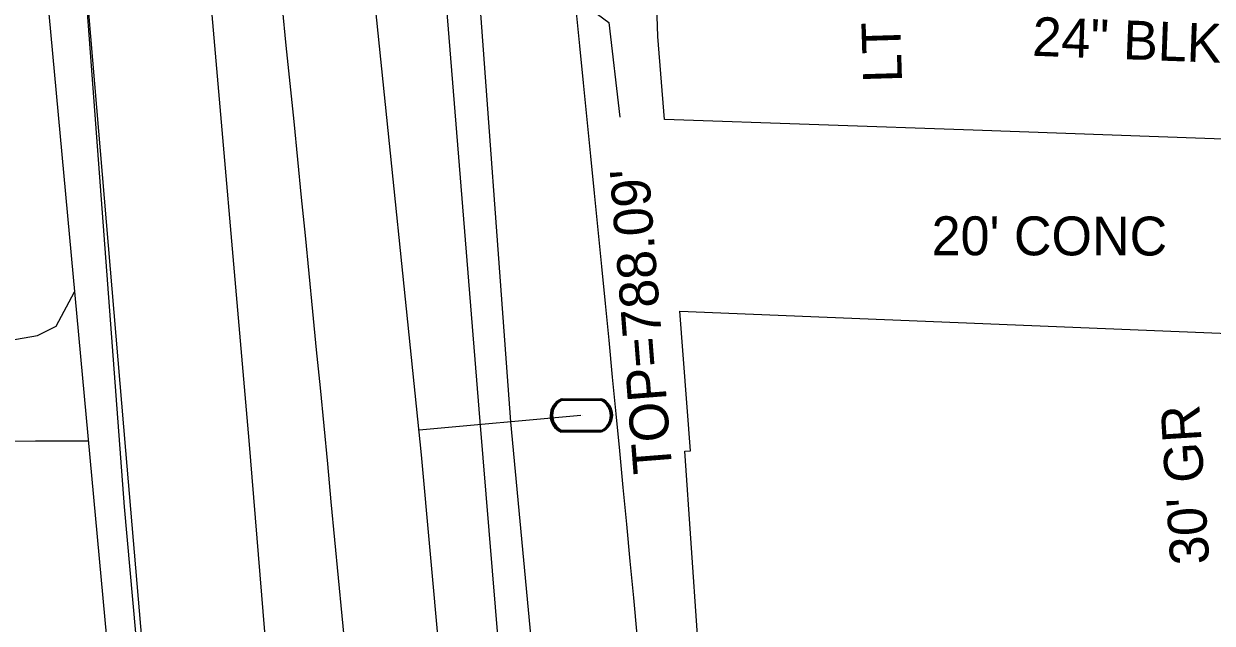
# Model space of a CAD drawing. Extents: x 1627482 to 1629573, y 760826 to 766301.
# Drawn here: x 1628290.6 to 1628412.7, y 765178.3 to 765240 of the extents above; entities that cross this region are included whole.
import ezdxf

# ---------------------------------------------------------------- set-up
doc = ezdxf.new("R2010")
doc.units = 0
for name, color, linetype in [('Exist Building Text', 7, 'Continuous'), ('Exist Horizontal Alignment', 7, 'Continuous'), ('Exist Right of Way Line', 7, 'Continuous'), ('Exist Roads EOP', 7, 'Continuous'), ('Exist Roads EOP Other', 7, 'Continuous'), ('Exist Roads EOP Other Text', 7, 'Continuous'), ('Exist Roads EOT', 7, 'Continuous'), ('Exist Roads Soil', 7, 'Continuous'), ('Exist Roads Soil Text', 7, 'Continuous'), ('Exist Structure Minor Catch Basin Leader', 7, 'Continuous'), ('Exist Structure Minor Catch Basin Top Elevation', 7, 'Continuous'), ('Exist Utilities Gas UG Line SUE LOS B', 7, 'Continuous'), ('Exist Utilities Other Pole Text', 7, 'Continuous'), ('Exist Utilities Water Meter CELL', 7, 'Continuous'), ('Exist Utilities Water UG Line SUE LOS B', 7, 'Continuous')]:
    doc.layers.add(name, color=color, linetype=linetype)

msp = doc.modelspace()

# ---------------------------------------------------------------- linework, layer by layer
at = {"layer": 'Exist Horizontal Alignment'}
msp.add_arc((1620544.28, 764447.73), 7813.36, 2.25819, 5.947048, dxfattribs=at)
at = {"layer": 'Exist Right of Way Line'}
msp.add_arc((1620544.28, 764447.73), 7843.36, 4.169003, 5.947048, dxfattribs=at)
at = {"layer": 'Exist Roads EOP'}
for points in [[(1628275.72, 765429.87), (1628315.6, 764998.34)], [(1628354.43, 765051.34), (1628349.75, 765100.45), (1628345.26, 765150.11), (1628340.67, 765199.02), (1628329.68, 765348.79)]]:
    msp.add_lwpolyline(points, dxfattribs=at)
at = {"layer": 'Exist Roads EOP Other'}
for points in [[(1628227.6, 765206.08), (1628250.03, 765206.33), (1628265.71, 765206.82), (1628277.78, 765207.1), (1628282.59, 765207.11), (1628289.08, 765207.38), (1628292.04, 765207.88), (1628293.95, 765208.86), (1628295.82, 765212.37)], [(1628297.24, 765197.03), (1628291.84, 765197.01), (1628281.78, 765196.91), (1628275.99, 765196.75), (1628262.37, 765196.22), (1628246.83, 765195.73), (1628233.2, 765195.6), (1628223.66, 765195.35), (1628223.39, 765205.83)]]:
    msp.add_lwpolyline(points, dxfattribs=at)
at = {"layer": 'Exist Roads EOT'}
for points in [[(1628321.8, 765097.93), (1628317.82, 765147.67), (1628313.79, 765197.09), (1628309.5, 765246.44), (1628305.25, 765296.01), (1628300.47, 765345.4), (1628295.75, 765394.23), (1628290.92, 765443.38), (1628286.2, 765493), (1628281.48, 765542.67), (1628276.9, 765591.66), (1628272.08, 765640.85), (1628267.39, 765690.37), (1628262.64, 765739.28), (1628257.97, 765789.11), (1628253.23, 765838.22), (1628248.39, 765887.64), (1628243.39, 765938.8), (1628238.58, 765988.56), (1628233.82, 766039.14), (1628229.1, 766088.8), (1628224.69, 766136.81)], [(1628314.55, 765029.12), (1628313.14, 765048.13), (1628309.33, 765096.73), (1628305.37, 765146.19), (1628301.1, 765196.07), (1628296.94, 765245.56), (1628292.62, 765294.59), (1628289.87, 765303.96), (1628287.14, 765334.52), (1628286.34, 765344.22)], [(1628364.1, 764792.12), (1628361.32, 764852.72), (1628359.01, 764902.56), (1628356.32, 764952.1), (1628353.22, 765001.24), (1628349.59, 765050.89), (1628345.67, 765099.92), (1628341.6, 765149.64), (1628337.53, 765199.06), (1628333.54, 765248.34)]]:
    msp.add_lwpolyline(points, dxfattribs=at)
at = {"layer": 'Exist Roads Soil'}
for points in [[(1628477.41, 765226.07), (1628435.8, 765227.31), (1628388.2, 765229), (1628356.47, 765230.12), (1628355.78, 765238.63), (1628355.29, 765253.22)], [(1628359.84, 765177.08), (1628358.57, 765195.99), (1628359.15, 765196.02), (1628358.04, 765210.4), (1628430.39, 765207.45), (1628479.28, 765205.18)]]:
    msp.add_lwpolyline(points, dxfattribs=at)
at = {"layer": 'Exist Structure Minor Catch Basin Leader'}
msp.add_lwpolyline([(1628338.57, 765249.05), (1628350.74, 765240.07), (1628351.89, 765230.35)], dxfattribs=at)
at = {"layer": 'Exist Utilities Gas UG Line SUE LOS B'}
msp.add_lwpolyline([(1628199.46, 764849.74), (1628245.39, 764843.93), (1628286.91, 764842.44), (1628323.21, 764841.89), (1628321.41, 764890.52), (1628318.08, 764974.07), (1628312.79, 765045.73), (1628307.65, 765115.94), (1628300.97, 765190.25), (1628294.72, 765274.13), (1628289.3, 765336.67), (1628283.53, 765391.1), (1628278.4, 765447.27), (1628276.21, 765471.83)], dxfattribs=at)
at = {"layer": 'Exist Utilities Water Meter CELL'}
for p, q in [((1628347.88, 765199.66), (1628347.88, 765199.66)), ((1628347.99, 765199.68), (1628347.99, 765199.68))]:
    msp.add_line(p, q, dxfattribs=at)
for points in [[(1628345.84, 765201.36), (1628349.91, 765201.36)], [(1628345.84, 765201.23), (1628349.91, 765201.23)], [(1628345.95, 765201.38), (1628350.03, 765201.38)], [(1628345.95, 765201.24), (1628350.03, 765201.24)], [(1628349.91, 765198.1), (1628345.81, 765198.1)], [(1628349.91, 765197.96), (1628345.81, 765197.96)], [(1628350.03, 765198.11), (1628345.93, 765198.11)], [(1628350.03, 765197.98), (1628345.93, 765197.98)]]:
    msp.add_lwpolyline(points, dxfattribs=at)
for centre, radius, start, end in [((1628346.57, 765199.66), 1.86, 113.178, 245.9794), ((1628346.68, 765199.67), 1.86, 113.178, 245.9794), ((1628346.58, 765199.66), 1.73, 115.3009, 243.7824), ((1628346.69, 765199.67), 1.73, 115.3009, 243.7824), ((1628349.17, 765199.67), 1.86, 293.6483, 66.3084), ((1628349.18, 765199.66), 1.73, 295.1272, 64.8728), ((1628349.28, 765199.68), 1.86, 293.6483, 66.3084), ((1628349.3, 765199.68), 1.73, 295.1272, 64.8728)]:
    msp.add_arc(centre, radius, start, end, dxfattribs=at)
at = {"layer": 'Exist Utilities Water UG Line SUE LOS B'}
msp.add_line((1628347.88, 765199.66), (1628331.25, 765198.14), dxfattribs=at)
msp.add_lwpolyline([(1628407.24, 763655.16), (1628402.4, 763754.94), (1628399.06, 763856.51), (1628396.12, 763915.33), (1628393.3, 763992.46), (1628390.7, 764066.34), (1628386.72, 764168.39), (1628382.56, 764256.29), (1628378.23, 764373.67), (1628375.54, 764455.63), (1628372.03, 764542.25), (1628370.17, 764583.36), (1628366.9, 764671.42), (1628365.27, 764739.23), (1628362.16, 764808.05), (1628361.5, 764823.25), (1628356.13, 764896.21), (1628352.11, 764986.77), (1628341.94, 765081.92), (1628331.48, 765195.63), (1628321.82, 765290.23), (1628312.98, 765379.55), (1628303.79, 765478.36)], dxfattribs=at)

# ---------------------------------------------------------------- texts
at = {"layer": 'Exist Building Text'}
msp.add_text('24" BLK WALL', height=4, rotation=357.8286, dxfattribs=at).set_placement((1628394.21, 765236.67))
at = {"layer": 'Exist Roads EOP Other Text'}
msp.add_text("20' CONC", height=4, rotation=359.9161, dxfattribs=at).set_placement((1628383.91, 765216.15))
at = {"layer": 'Exist Roads Soil Text'}
msp.add_text("30' GR", height=4, rotation=93.6422, dxfattribs=at).set_placement((1628412.46, 765184.43))
at = {"layer": 'Exist Structure Minor Catch Basin Top Elevation'}
msp.add_text("TOP=788.09'", height=4, rotation=94.4835, dxfattribs=at).set_placement((1628357.28, 765193.81))
at = {"layer": 'Exist Utilities Other Pole Text'}
msp.add_text('LT', height=4, rotation=91.7713, dxfattribs=at).set_placement((1628380.88, 765233.95))

doc.saveas('drawing.dxf')
